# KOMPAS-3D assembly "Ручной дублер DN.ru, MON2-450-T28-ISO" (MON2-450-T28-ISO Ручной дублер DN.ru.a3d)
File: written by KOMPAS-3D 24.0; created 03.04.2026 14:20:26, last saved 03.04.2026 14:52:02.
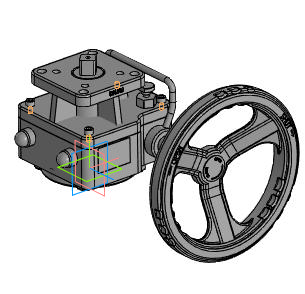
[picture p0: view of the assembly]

Document properties: Автор: R2D2; Полное имя файла: E:\Работа\Зайцев\Аксессуары для пневмоприводов\Ручной дублер DN.ru\MON2-450-T28-ISO Ручной дублер DN.ru\исходные материалы\MON2-450-T28-ISO Ручной дублер DN.ru.a3d

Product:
- Component [detail]: Деталь1  | qty 1  | pos. 1  | Масса: 10.922817; Автор: R2D2; additional columns: Типовые; source file: 3.m3d
- Component [detail]: Деталь1  | qty 1  | pos. 1  | Масса: 10.922817; Автор: R2D2; additional columns: Типовые; source file: 2.m3d
- Component [detail]: Деталь1  | qty 1  | Масса: 10.922817; Автор: R2D2; additional columns: Типовые; source file: 1.m3d
- Component [detail]: Деталь 2  | qty 1  | pos. 2  | Масса: 2.361285; Автор: R2D2; additional columns: Типовые; source file: Деталь 2 Деталь 2.m3d
- Component [standard]: Hexagon socket head cap screw ISO 4762 - М6 x 10  | qty 4  | Материал: Не определено (density 0 kg/m3); Масса: 0.0047; Раздел спецификации: Стандартные изделия; Рассекать на разрезах: no
- Part/product: Ручной дублер DN.ru  | designation MON2-450-T28-ISO
    Масса: 4.5
    Раздел спецификации: Прочие изделия
    Примечание: D290-00337

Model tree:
1. Эскиз:1  (with: Грань.Операция без истории:1, Ребро.Операция без истории:1)
2. Эскиз:2  (with: Грань.Операция без истории:1, Ребро.Операция без истории:1)
3. Элемент выдавливания:1
     Расстояние 2 = 22
4. Эскиз:3  (with: Грань.Операция без истории:1, Ребро.Операция без истории:1)
5. Элемент выдавливания:2
     Расстояние 2 = 13
6. Эскиз:4  (with: Грань.Операция без истории:1, Ребро.Операция без истории:1, Ребро.Элемент выдавливания:1)
7. Элемент выдавливания:3  (with: Грань.Операция без истории:1, Грань.Элемент выдавливания:5)
     Расстояние 2 = 16; Расстояние = 10; Расстояние = -133; Расстояние = -178

Referenced files in E:\Работа\Зайцев\Аксессуары для пневмоприводов\Ручной дублер DN.ru\MON2-450-T28-ISO Ручной дублер DN.ru\исходные материалы\: 3.m3d, 2.m3d, 1.m3d, Деталь 2 Деталь 2.m3d
Referenced files in C:\Program Files\ASCON\KOMPAS-3D v24\Libs\PolynomLib\DATA\vault\Methods\Kompas\3D\: PLib_Screw_DIN_7984_1500.m3d
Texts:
  Hexagon socket head cap screw
  BOSimple***PART:86906dfe-320b-4a65-fedb-73bd2ba9e651***SHORTLOC:A259_235BDFABBEFC4171[1;10;6;-;Undefined]
  Программные изделия  и базы данных
  MON2-450-T28-ISO
  Деталь1 Деталь1
  Деталь 2 Деталь 2
  Hexagon socket head cap screw ISO 4762 - М6 x 10 (1)
  Hexagon socket head cap screw ISO 4762 - М6 x 10 (2)
  Hexagon socket head cap screw ISO 4762 - М6 x 10 (4)
  Hexagon socket head cap screw ISO 4762 - М6 x 10 (6)
  Ось Y.Начало координат
  Плоскость ZX.Начало координат
  Плоскость XY.Начало координат
  Ось Z.Начало координат
  Плоскость ZY.Начало координат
